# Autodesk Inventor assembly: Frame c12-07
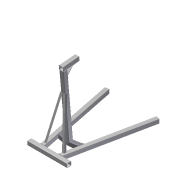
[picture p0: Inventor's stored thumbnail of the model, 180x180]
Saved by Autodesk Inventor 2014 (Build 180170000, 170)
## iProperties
Created: 2011-01
Part Number: Frame c12-07
Document SubType Name: Assembly
Designer: Thom Tremblay
_FrameDoc: Frame Assembly
_Version: 15.0.0
Author: Thom Tremblay
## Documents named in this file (20)
- C:\Inventor 2014 Essentials\Assemblies\Chapter 12\Frame\Frame c12-07.iam
- C:\Inventor 2014 Essentials\Assemblies\Chapter 12\Frame\Skeleton-c12-07.ipt
- C:\Inventor 2014 Essentials\Assemblies\Chapter 12\Frame\ANSI L 1.5 x 1.5 x 3_16 00000003.ipt
- ANSI L 1.5 x 1.5 x 3_16 00000003.ipt
- C:\Inventor 2014 Essentials\Assemblies\Chapter 12\Frame\ANSI L 1.5 x 1.5 x 3_16 00000004.ipt
- ANSI L 1.5 x 1.5 x 3_16 00000004.ipt
- C:\Inventor 2014 Essentials\Assemblies\Chapter 12\Frame\ANSI 2 1_4x5_16 00000005.ipt
- ANSI 2 1_4x5_16 00000005.ipt
- C:\Inventor 2014 Essentials\Assemblies\Chapter 12\Frame\ANSI 3x3x3_16 00000030.ipt
- ANSI 3x3x3_16 00000030.ipt
- C:\Inventor 2014 Essentials\Assemblies\Chapter 12\Frame\ANSI 3x3x3_16 00000032.ipt
- ANSI 3x3x3_16 00000032.ipt
- C:\Inventor 2014 Essentials\Assemblies\Chapter 12\Frame\ANSI 3x3x3_16 00000033.ipt
- ANSI 3x3x3_16 00000033.ipt
- C:\Inventor 2014 Essentials\Assemblies\Chapter 12\Frame\ANSI 3x3x3_16 00000034.ipt
- ANSI 3x3x3_16 00000034.ipt
- C:\Inventor 2014 Essentials\Assemblies\Chapter 12\Frame\ANSI 3x3x3_16 00000036.ipt
- ANSI 3x3x3_16 00000036.ipt
- C:\Inventor 2014 Essentials\Assemblies\Chapter 12\Frame\ANSI 3x3x3_16 00000061.ipt
- ANSI 3x3x3_16 00000061.ipt
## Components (10 placed, 10 different names)
1. Frame Reference Model
2. ANSI L 1.5 x 1.5 x 3_16 00000003:1
3. ANSI L 1.5 x 1.5 x 3_16 00000004:1
4. ANSI 2 1_4x5_16 00000005:1
5. ANSI 3x3x3_16 00000030:1
6. ANSI 3x3x3_16 00000032:1
7. ANSI 3x3x3_16 00000033:1
8. ANSI 3x3x3_16 00000034:1
9. ANSI 3x3x3_16 00000036:1
10. ANSI 3x3x3_16 00000061:1
